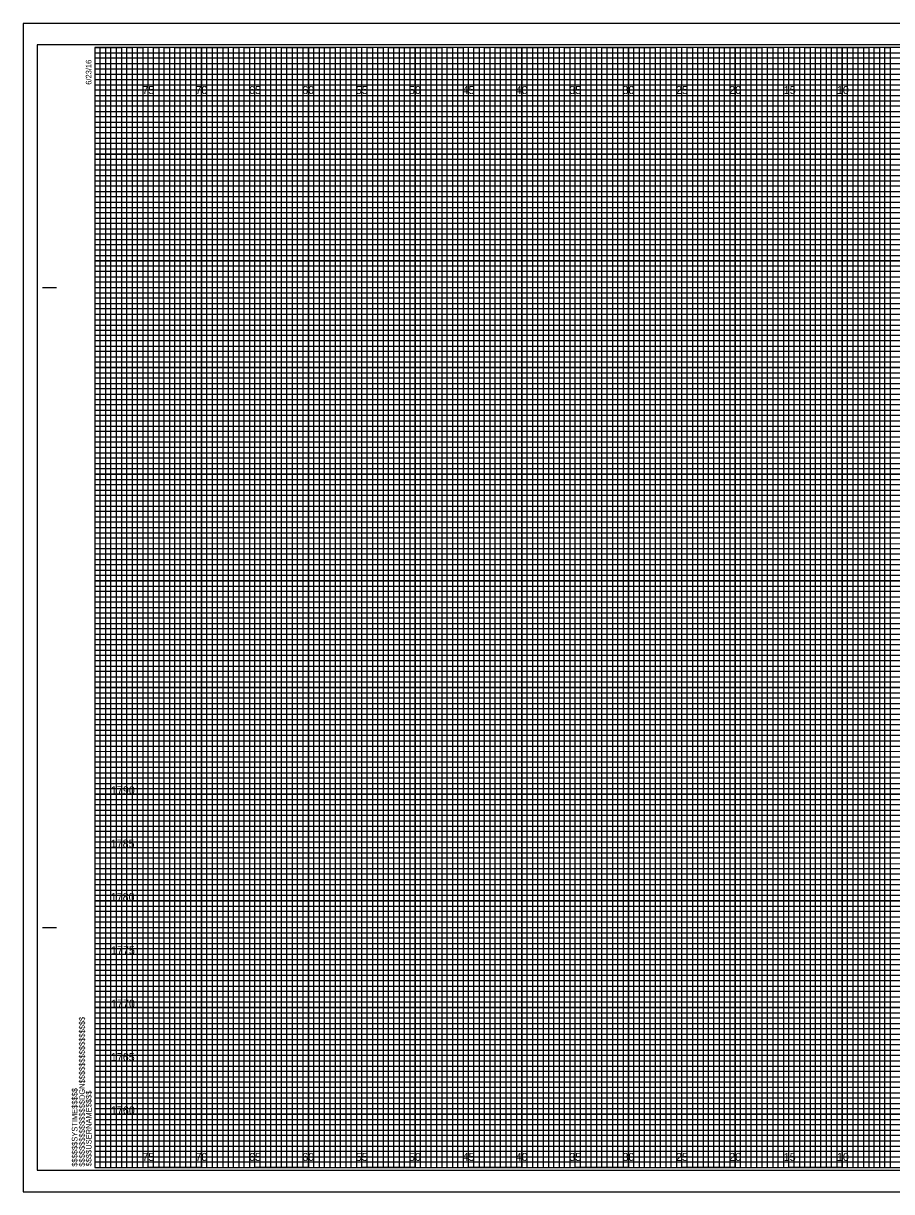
# Model space of a CAD drawing. Extents: x 224 to 392, y 1 to 440.
# Drawn here: x 223.6 to 304.9, y 331 to 440.5 of the extents above; entities that cross this region are included whole.
import ezdxf

# ---------------------------------------------------------------- set-up
doc = ezdxf.new("R2010")
doc.units = 0
for name, color, linetype in [('Prop Grid Mask', 7, 'Continuous'), ('Prop XS Elevation Labels', 7, 'Continuous'), ('Sheet Cross Section CELL', 7, 'Continuous'), ('Sheet Cross Section Grid Major CELL', 7, 'Continuous'), ('Sheet Cross Section Grid Middle CELL', 7, 'Continuous'), ('Sheet Cross Section Grid Minor 1 CELL', 7, 'Continuous'), ('Sheet Cross Section Grid Minor 2 CELL', 7, 'Continuous'), ('Sheet Cutting Line CELL', 7, 'Continuous'), ('Sheet DOT Grid CELL', 7, 'Continuous'), ('Sheet Plot Border Inside CELL', 7, 'Continuous'), ('Sheet Plot Border Outside CELL', 7, 'Continuous')]:
    doc.layers.add(name, color=color, linetype=linetype)

msp = doc.modelspace()

# ---------------------------------------------------------------- linework, layer by layer
at = {"layer": 'Sheet Cross Section CELL'}
for p, q in [((225.36, 415.71), (226.61, 415.71)), ((225.41, 415.71), (226.66, 415.71)), ((225.36, 355.71), (226.61, 355.71)), ((225.41, 355.71), (226.66, 355.71)), ((230.26, 333.21), (230.26, 333.21)), ((230.26, 333.21), (230.26, 333.21)), ((230.26, 333.21), (230.26, 333.21)), ((230.26, 333.21), (230.26, 333.21)), ((230.26, 333.21), (230.26, 333.21)), ((230.26, 333.21), (230.26, 333.21)), ((230.26, 333.21), (230.26, 333.21))]:
    msp.add_line(p, q, dxfattribs=at)
msp.add_lwpolyline([(390.26, 438.21), (230.26, 438.21), (230.26, 333.21), (390.26, 333.21)], close=True, dxfattribs=at)
at = {"layer": 'Sheet Cross Section Grid Major CELL'}
for p, q in [((235.26, 438.21), (230.26, 438.21)), ((235.26, 333.21), (235.26, 438.21)), ((245.26, 438.21), (240.26, 438.21)), ((240.26, 438.21), (240.26, 333.21)), ((245.26, 333.21), (245.26, 438.21)), ((255.26, 438.21), (250.26, 438.21)), ((250.26, 438.21), (250.26, 333.21)), ((255.26, 333.21), (255.26, 438.21)), ((265.26, 438.21), (260.26, 438.21)), ((260.26, 438.21), (260.26, 333.21)), ((265.26, 333.21), (265.26, 438.21)), ((275.26, 438.21), (270.26, 438.21)), ((270.26, 438.21), (270.26, 333.21)), ((275.26, 333.21), (275.26, 438.21)), ((285.26, 438.21), (280.26, 438.21)), ((280.26, 438.21), (280.26, 333.21)), ((285.26, 333.21), (285.26, 438.21)), ((295.26, 438.21), (290.26, 438.21)), ((290.26, 438.21), (290.26, 333.21)), ((295.26, 333.21), (295.26, 438.21)), ((305.26, 438.21), (300.26, 438.21)), ((300.26, 438.21), (300.26, 333.21)), ((240.26, 333.21), (235.26, 333.21)), ((250.26, 333.21), (245.26, 333.21)), ((260.26, 333.21), (255.26, 333.21)), ((270.26, 333.21), (265.26, 333.21)), ((280.26, 333.21), (275.26, 333.21)), ((290.26, 333.21), (285.26, 333.21)), ((300.26, 333.21), (295.26, 333.21))]:
    msp.add_line(p, q, dxfattribs=at)
for points in [[(230.26, 433.21), (390.26, 433.21), (390.26, 428.21), (230.26, 428.21)], [(230.26, 423.21), (390.26, 423.21), (390.26, 418.21), (230.26, 418.21)], [(230.26, 413.21), (390.26, 413.21), (390.26, 408.21), (230.26, 408.21)], [(230.26, 403.21), (390.26, 403.21), (390.26, 398.21), (230.26, 398.21)], [(230.26, 393.21), (390.26, 393.21), (390.26, 388.21), (230.26, 388.21)], [(230.26, 383.21), (390.26, 383.21), (390.26, 378.21), (230.26, 378.21)], [(230.26, 373.21), (390.26, 373.21), (390.26, 368.21), (230.26, 368.21)], [(230.26, 363.21), (390.26, 363.21), (390.26, 358.21), (230.26, 358.21)], [(230.26, 353.21), (390.26, 353.21), (390.26, 348.21), (230.26, 348.21)], [(230.26, 343.21), (390.26, 343.21), (390.26, 338.21), (230.26, 338.21)]]:
    msp.add_lwpolyline(points, dxfattribs=at)
at = {"layer": 'Sheet Cross Section Grid Middle CELL'}
for points in [[(230.26, 438.21), (232.76, 438.21), (232.76, 333.21), (237.76, 333.21), (237.76, 438.21), (242.76, 438.21), (242.76, 333.21), (247.76, 333.21), (247.76, 438.21), (252.76, 438.21), (252.76, 333.21), (257.76, 333.21), (257.76, 438.21), (262.76, 438.21), (262.76, 333.21), (267.76, 333.21), (267.76, 438.21), (272.76, 438.21), (272.76, 333.21), (277.76, 333.21), (277.76, 438.21), (282.76, 438.21), (282.76, 333.21), (287.76, 333.21), (287.76, 438.21), (292.76, 438.21), (292.76, 333.21), (297.76, 333.21), (297.76, 438.21), (302.76, 438.21), (302.76, 333.21), (307.76, 333.21)], [(230.26, 435.71), (367.76, 435.71)], [(230.26, 425.71), (390.26, 425.71), (390.26, 430.71), (230.26, 430.71)], [(230.26, 415.71), (390.26, 415.71), (390.26, 420.71), (230.26, 420.71)], [(230.26, 405.71), (390.26, 405.71), (390.26, 410.71), (230.26, 410.71)], [(230.26, 395.71), (390.26, 395.71), (390.26, 400.71), (230.26, 400.71)], [(230.26, 385.71), (390.26, 385.71), (390.26, 390.71), (230.26, 390.71)], [(230.26, 375.71), (390.26, 375.71), (390.26, 380.71), (230.26, 380.71)], [(230.26, 365.71), (390.26, 365.71), (390.26, 370.71), (230.26, 370.71)], [(230.26, 355.71), (390.26, 355.71), (390.26, 360.71), (230.26, 360.71)], [(230.26, 345.71), (390.26, 345.71), (390.26, 350.71), (230.26, 350.71)], [(230.26, 335.71), (390.26, 335.71), (390.26, 340.71), (230.26, 340.71)]]:
    msp.add_lwpolyline(points, dxfattribs=at)
at = {"layer": 'Sheet Cross Section Grid Minor 1 CELL'}
for p, q in [((230.26, 437.71), (360.26, 437.71)), ((360.26, 437.2), (230.26, 437.2)), ((230.26, 437.2), (230.26, 436.71)), ((230.26, 436.71), (360.26, 436.71)), ((360.26, 436.16), (230.26, 436.16)), ((230.26, 436.16), (230.26, 435.21)), ((230.26, 435.21), (390.26, 435.21))]:
    msp.add_line(p, q, dxfattribs=at)
for points in [[(230.26, 434.71), (365.26, 434.71), (390.26, 434.71), (390.26, 434.21), (230.26, 434.21)], [(230.26, 433.71), (390.26, 433.71), (390.26, 432.71), (230.26, 432.71)], [(230.26, 432.21), (390.26, 432.21), (390.26, 431.71), (230.26, 431.7)], [(230.26, 431.21), (390.26, 431.21), (390.26, 430.21), (230.26, 430.21)], [(230.26, 429.71), (390.26, 429.71), (390.26, 429.21), (230.26, 429.21)], [(230.26, 428.71), (390.26, 428.71), (390.26, 427.71), (230.26, 427.71)], [(230.26, 427.21), (390.26, 427.21), (390.26, 426.71), (230.26, 426.71)], [(230.26, 426.21), (390.26, 426.21), (390.26, 425.21), (230.26, 425.21)], [(230.26, 424.71), (390.26, 424.71), (390.26, 424.21), (230.26, 424.21)], [(230.26, 423.71), (390.26, 423.71), (390.26, 422.71), (230.26, 422.71)], [(230.26, 422.21), (390.26, 422.21), (390.26, 421.71), (230.26, 421.71)], [(230.26, 421.21), (390.26, 421.21), (390.26, 420.19), (390.26, 419.71), (390.26, 419.21), (230.26, 419.21)], [(230.26, 420.21), (390.26, 420.21), (390.26, 419.71), (230.26, 419.71)], [(230.26, 418.71), (390.26, 418.71), (390.26, 417.71), (230.26, 417.73)], [(230.26, 417.73), (390.26, 417.71), (390.26, 417.21), (230.26, 417.21)], [(230.26, 416.71), (390.26, 416.71), (390.26, 416.21), (230.26, 416.21)], [(230.26, 415.21), (390.26, 415.21), (390.26, 414.71), (230.26, 414.71)], [(230.26, 414.21), (390.26, 414.21), (390.26, 413.71), (230.26, 413.71)], [(230.23, 412.66), (390.26, 412.66), (390.26, 412.15), (230.23, 412.15)], [(230.26, 411.71), (390.26, 411.71), (390.26, 411.21), (230.26, 411.21)], [(230.26, 410.21), (390.26, 410.21), (390.26, 409.71), (230.26, 409.71)], [(230.26, 409.21), (390.26, 409.21), (390.26, 408.71), (230.26, 408.71)], [(230.26, 407.71), (390.26, 407.71), (390.26, 407.21), (230.26, 407.21)], [(230.26, 406.71), (390.26, 406.71), (390.26, 406.21), (230.26, 406.21)], [(230.26, 405.21), (390.26, 405.21), (390.26, 404.71), (230.26, 404.71)], [(230.26, 404.21), (390.26, 404.21), (390.26, 403.71), (230.26, 403.71)], [(230.26, 402.71), (390.26, 402.71), (390.26, 402.2), (230.26, 402.21)], [(230.26, 401.71), (390.26, 401.71), (390.26, 401.21), (230.26, 401.21)], [(230.26, 400.21), (390.26, 400.21), (390.26, 399.71), (230.26, 399.71)], [(230.26, 399.21), (390.26, 399.21), (390.26, 398.71), (230.26, 398.71)], [(230.26, 397.71), (390.26, 397.71), (390.26, 397.21), (230.26, 397.21)], [(230.26, 396.71), (390.26, 396.71), (390.26, 396.21), (230.26, 396.21)], [(230.26, 395.21), (390.26, 395.21), (390.26, 394.71), (230.26, 394.71)], [(230.26, 394.21), (390.26, 394.21), (390.26, 393.71), (230.26, 393.71)], [(230.26, 392.71), (390.26, 392.71), (390.26, 392.21), (230.26, 392.21)], [(230.26, 391.71), (390.3, 391.67), (390.26, 391.21), (230.26, 391.21)], [(230.26, 390.21), (390.26, 390.21), (390.26, 389.71), (230.26, 389.71)], [(230.26, 389.21), (390.26, 389.21), (390.26, 388.71), (230.26, 388.71)], [(230.26, 387.71), (390.26, 387.71), (390.26, 387.21), (230.26, 387.21)], [(230.26, 386.71), (390.26, 386.71), (390.26, 386.21), (230.26, 386.21)], [(230.26, 385.21), (390.26, 385.21), (390.26, 384.71), (230.26, 384.71)], [(230.26, 384.21), (390.26, 384.21), (390.26, 383.71), (230.26, 383.71)], [(230.26, 382.71), (390.26, 382.71), (390.26, 382.21), (230.26, 382.21)], [(230.26, 381.71), (390.26, 381.71), (390.26, 381.21), (230.26, 381.21)], [(230.26, 380.21), (390.26, 380.21), (390.26, 379.71), (230.26, 379.71)], [(230.26, 379.21), (390.26, 379.21), (390.26, 378.71), (230.26, 378.71)], [(230.26, 377.71), (390.26, 377.71), (390.26, 377.21), (230.26, 377.21)], [(230.26, 376.71), (390.26, 376.71), (390.26, 376.21), (230.26, 376.21)], [(230.26, 375.21), (390.26, 375.21), (390.26, 374.71), (230.26, 374.71)], [(230.26, 374.21), (390.26, 374.21), (390.26, 373.71), (230.26, 373.71)], [(230.26, 372.71), (390.26, 372.71), (390.26, 372.2), (230.26, 372.21)], [(230.26, 371.71), (390.26, 371.71), (390.26, 371.21), (230.26, 371.21)], [(230.26, 370.21), (390.26, 370.21), (390.26, 369.71), (230.26, 369.71)], [(230.26, 369.21), (390.26, 369.21), (390.26, 368.71), (230.26, 368.71)], [(230.26, 367.71), (390.26, 367.71), (390.26, 367.21), (230.26, 367.21)], [(230.26, 366.71), (390.26, 366.71), (390.26, 366.21), (230.26, 366.21)], [(230.26, 365.21), (390.26, 365.21), (390.26, 364.71), (230.26, 364.71)], [(230.26, 364.21), (390.26, 364.21), (390.26, 363.71), (230.26, 363.71)], [(230.26, 362.71), (390.26, 362.71), (390.26, 362.21), (230.26, 362.21)], [(230.26, 361.71), (390.3, 361.67), (390.26, 361.21), (230.26, 361.21)], [(230.26, 360.21), (390.26, 360.21), (390.26, 359.71), (230.26, 359.71)], [(230.26, 359.21), (390.26, 359.21), (390.26, 358.71), (230.26, 358.71)], [(230.26, 357.71), (390.26, 357.71), (390.26, 357.21), (230.26, 357.21)], [(230.26, 356.71), (390.26, 356.71), (390.26, 356.21), (230.26, 356.21)], [(230.26, 355.21), (390.26, 355.21), (390.26, 354.71), (230.26, 354.71)], [(230.26, 354.21), (390.26, 354.21), (390.26, 353.71), (230.26, 353.71)], [(230.26, 352.71), (390.26, 352.71), (390.26, 352.21), (230.26, 352.21)], [(230.26, 351.71), (390.26, 351.71), (390.26, 351.21), (230.26, 351.21)], [(230.26, 350.21), (390.26, 350.21), (390.26, 349.71), (230.26, 349.71)], [(230.26, 349.21), (390.26, 349.21), (390.26, 348.71), (230.26, 348.71)], [(230.26, 347.71), (390.26, 347.71), (390.26, 347.21), (230.26, 347.21)], [(230.26, 346.71), (390.26, 346.71), (390.26, 346.21), (230.26, 346.21)], [(230.26, 345.21), (390.26, 345.21), (390.26, 344.71), (230.26, 344.71)], [(230.26, 344.21), (390.26, 344.21), (390.26, 343.71), (230.26, 343.71)], [(230.26, 342.71), (390.26, 342.71), (390.26, 342.21), (230.26, 342.21)], [(230.26, 341.71), (390.26, 341.71), (390.26, 341.21), (230.26, 341.21)], [(230.26, 340.21), (390.26, 340.21), (390.26, 339.71), (230.26, 339.71)], [(230.26, 339.21), (390.26, 339.21), (390.26, 338.71), (230.26, 338.71)], [(230.26, 337.71), (390.26, 337.71), (390.26, 337.21), (230.26, 337.21)], [(230.26, 336.71), (390.26, 336.71), (390.26, 336.21), (230.26, 336.21)], [(230.26, 335.21), (390.26, 335.21), (390.26, 334.71), (230.26, 334.71)], [(230.26, 334.21), (390.26, 334.21), (390.26, 333.71), (230.26, 333.71)]]:
    msp.add_lwpolyline(points, dxfattribs=at)
at = {"layer": 'Sheet Cross Section Grid Minor 2 CELL'}
for points in [[(230.26, 333.21), (230.76, 333.21), (230.76, 438.21), (231.26, 438.21), (231.26, 333.21)], [(231.26, 333.21), (231.76, 333.21), (231.76, 438.21), (232.26, 438.21), (232.26, 333.21)], [(232.76, 333.21), (233.26, 333.21), (233.26, 438.21), (233.76, 438.21), (233.76, 333.21)], [(233.76, 333.21), (234.26, 333.21), (234.26, 438.21), (234.76, 438.21), (234.76, 333.21)], [(235.26, 333.21), (235.76, 333.21), (235.76, 438.21), (236.26, 438.21), (236.26, 333.21)], [(236.26, 333.21), (236.76, 333.21), (236.76, 438.21), (237.26, 438.21), (237.26, 333.21)], [(237.76, 333.21), (238.26, 333.21), (238.26, 438.21), (238.76, 438.21), (238.76, 333.21)], [(238.76, 333.21), (239.26, 333.21), (239.26, 438.21), (239.76, 438.21), (239.76, 333.21)], [(240.26, 333.21), (240.76, 333.21), (240.76, 438.21), (241.26, 438.21), (241.26, 333.21)], [(241.26, 333.21), (241.76, 333.21), (241.76, 438.21), (242.26, 438.21), (242.26, 333.21)], [(242.76, 333.21), (243.26, 333.21), (243.26, 438.21), (243.76, 438.21), (243.76, 333.21)], [(243.76, 333.21), (244.26, 333.21), (244.26, 438.21), (244.76, 438.21), (244.76, 333.21)], [(245.26, 333.21), (245.76, 333.21), (245.76, 438.21), (246.26, 438.21), (246.26, 333.21)], [(246.26, 333.21), (246.76, 333.21), (246.76, 438.21), (247.26, 438.21), (247.26, 333.21)], [(247.76, 333.21), (248.26, 333.21), (248.26, 438.21), (248.76, 438.21), (248.76, 333.21)], [(248.76, 333.21), (249.26, 333.21), (249.26, 438.21), (249.76, 438.21), (249.76, 333.21)], [(250.26, 333.21), (250.76, 333.21), (250.76, 438.21), (251.26, 438.21), (251.26, 333.21)], [(251.26, 333.21), (251.76, 333.21), (251.76, 438.21), (252.26, 438.21), (252.26, 333.21)], [(252.76, 333.21), (253.26, 333.21), (253.26, 438.21), (253.76, 438.21), (253.76, 333.21)], [(253.76, 333.21), (254.26, 333.21), (254.26, 438.21), (254.76, 438.21), (254.76, 333.21)], [(255.26, 333.21), (255.76, 333.21), (255.76, 438.21), (256.26, 438.21), (256.26, 333.21)], [(256.26, 333.21), (256.76, 333.21), (256.76, 438.21), (257.26, 438.21), (257.26, 333.21)], [(257.76, 333.21), (258.26, 333.21), (258.26, 438.21), (258.76, 438.21), (258.76, 333.21)], [(258.76, 333.21), (259.26, 333.21), (259.26, 438.21), (259.76, 438.21), (259.76, 333.21)], [(260.26, 333.21), (260.76, 333.21), (260.76, 438.21), (261.26, 438.21), (261.26, 333.21)], [(261.26, 333.21), (261.76, 333.21), (261.76, 438.21), (262.26, 438.21), (262.26, 333.21)], [(262.76, 333.21), (263.26, 333.21), (263.26, 438.21), (263.76, 438.21), (263.76, 333.21)], [(263.76, 333.21), (264.26, 333.21), (264.26, 438.21), (264.76, 438.21), (264.76, 333.21)], [(265.26, 333.21), (265.76, 333.21), (265.76, 438.21), (266.26, 438.21), (266.26, 333.21)], [(266.26, 333.21), (266.76, 333.21), (266.76, 438.21), (267.26, 438.21), (267.26, 333.21)], [(267.76, 333.21), (268.26, 333.21), (268.26, 438.21), (268.76, 438.21), (268.76, 333.21)], [(268.76, 333.21), (269.26, 333.21), (269.26, 438.21), (269.76, 438.21), (269.76, 333.21)], [(270.26, 333.21), (270.76, 333.21), (270.76, 438.21), (271.26, 438.21), (271.26, 333.21)], [(271.26, 333.21), (271.76, 333.21), (271.76, 438.21), (272.26, 438.21), (272.26, 333.21)], [(272.76, 333.21), (273.26, 333.21), (273.26, 438.21), (273.76, 438.21), (273.76, 333.21)], [(273.76, 333.21), (274.26, 333.21), (274.26, 438.21), (274.76, 438.21), (274.76, 333.21)], [(275.26, 333.21), (275.76, 333.21), (275.76, 438.21), (276.26, 438.21), (276.26, 333.21)], [(276.26, 333.21), (276.76, 333.21), (276.76, 438.21), (277.26, 438.21), (277.26, 333.21)], [(277.76, 333.21), (278.26, 333.21), (278.26, 438.21), (278.76, 438.21), (278.76, 333.21)], [(278.76, 333.21), (279.26, 333.21), (279.26, 438.21), (279.76, 438.21), (279.76, 333.21)], [(280.26, 333.21), (280.76, 333.21), (280.76, 438.21), (281.26, 438.21), (281.26, 333.21)], [(281.26, 333.21), (281.76, 333.21), (281.76, 438.21), (282.26, 438.21), (282.26, 333.21)], [(282.76, 333.21), (283.26, 333.21), (283.26, 438.21), (283.76, 438.21), (283.76, 333.21)], [(283.76, 333.21), (284.26, 333.21), (284.26, 438.21), (284.76, 438.21), (284.76, 333.21)], [(285.26, 333.21), (285.76, 333.21), (285.76, 438.21), (286.26, 438.21), (286.26, 333.21)], [(286.26, 333.21), (286.76, 333.21), (286.76, 438.21), (287.26, 438.21), (287.26, 333.21)], [(287.76, 333.21), (288.26, 333.21), (288.26, 438.21), (288.76, 438.21), (288.76, 333.21)], [(288.76, 333.21), (289.26, 333.21), (289.26, 438.21), (289.76, 438.21), (289.76, 333.21)], [(290.26, 333.21), (290.76, 333.21), (290.76, 438.21), (291.26, 438.21), (291.26, 333.21)], [(291.26, 333.21), (291.76, 333.21), (291.76, 438.21), (292.26, 438.21), (292.26, 333.21)], [(292.76, 333.21), (293.26, 333.21), (293.26, 438.21), (293.76, 438.21), (293.76, 333.21)], [(293.76, 333.21), (294.26, 333.21), (294.26, 438.21), (294.76, 438.21), (294.76, 333.21)], [(295.26, 333.21), (295.76, 333.21), (295.76, 438.21), (296.26, 438.21), (296.26, 333.21)], [(296.26, 333.21), (296.76, 333.21), (296.76, 438.21), (297.26, 438.21), (297.26, 333.21)], [(297.76, 333.21), (298.26, 333.21), (298.26, 438.21), (298.76, 438.21), (298.76, 333.21)], [(298.76, 333.21), (299.26, 333.21), (299.26, 438.21), (299.76, 438.21), (299.76, 333.21)], [(300.26, 333.21), (300.76, 333.21), (300.76, 438.21), (301.26, 438.21), (301.26, 333.21)], [(301.26, 333.21), (301.76, 333.21), (301.76, 438.21), (302.26, 438.21), (302.26, 333.21)], [(302.76, 333.21), (303.26, 333.21), (303.26, 438.21), (303.76, 438.21), (303.76, 333.21)], [(303.76, 333.21), (304.26, 333.21), (304.26, 438.21), (304.76, 438.21), (304.76, 333.21)]]:
    msp.add_lwpolyline(points, dxfattribs=at)
at = {"layer": 'Sheet Cutting Line CELL'}
for p, q in [((391.91, 440.46), (223.56, 440.46)), ((223.56, 440.46), (223.56, 330.96)), ((223.56, 330.96), (391.91, 330.96))]:
    msp.add_line(p, q, dxfattribs=at)
at = {"layer": 'Sheet DOT Grid CELL'}
for p, q in [((235.26, 333.21), (235.26, 438.21)), ((240.26, 333.21), (240.26, 438.21)), ((245.26, 333.21), (245.26, 438.21)), ((250.26, 333.21), (250.26, 438.21)), ((255.26, 333.21), (255.26, 438.21)), ((260.26, 333.21), (260.26, 438.21)), ((265.26, 333.21), (265.26, 438.21)), ((270.26, 333.21), (270.26, 438.21)), ((275.26, 333.21), (275.26, 438.21)), ((280.26, 333.21), (280.26, 438.21)), ((285.26, 333.21), (285.26, 438.21)), ((290.26, 333.21), (290.26, 438.21)), ((295.26, 333.21), (295.26, 438.21)), ((300.26, 333.21), (300.26, 438.21)), ((230.26, 433.21), (390.26, 433.21)), ((230.26, 428.21), (390.26, 428.21)), ((230.26, 423.21), (390.26, 423.21)), ((230.26, 418.21), (390.26, 418.21)), ((230.26, 413.21), (390.26, 413.21)), ((230.26, 408.21), (390.26, 408.21)), ((230.26, 403.21), (390.26, 403.21)), ((230.26, 398.21), (390.26, 398.21)), ((230.26, 393.21), (390.26, 393.21)), ((230.26, 388.21), (390.26, 388.21)), ((230.26, 383.21), (390.26, 383.21)), ((230.26, 378.21), (390.26, 378.21)), ((230.26, 373.21), (390.26, 373.21)), ((230.26, 368.21), (390.26, 368.21)), ((230.26, 363.21), (390.26, 363.21)), ((230.26, 358.21), (390.26, 358.21)), ((230.26, 353.21), (390.26, 353.21)), ((230.26, 348.21), (390.26, 348.21)), ((230.26, 343.21), (390.26, 343.21)), ((230.26, 338.21), (390.26, 338.21))]:
    msp.add_line(p, q, dxfattribs=at)
at = {"layer": 'Sheet Plot Border Inside CELL'}
msp.add_lwpolyline([(224.86, 332.96), (391.46, 332.96), (391.46, 438.46), (224.86, 438.46)], close=True, dxfattribs=at)
at = {"layer": 'Sheet Plot Border Outside CELL'}
msp.add_lwpolyline([(223.56, 330.96), (391.91, 330.96), (391.91, 440.46), (223.56, 440.46)], close=True, dxfattribs=at)

# ---------------------------------------------------------------- texts
at = {"layer": 'Prop Grid Mask'}
for s, p in [('75', (234.71, 433.84)), ('70', (239.69, 433.84)), ('65', (244.71, 433.84)), ('60', (249.69, 433.84)), ('55', (254.71, 433.84)), ('50', (259.69, 433.84)), ('45', (264.71, 433.84)), ('40', (269.69, 433.84)), ('35', (274.71, 433.84)), ('30', (279.69, 433.84)), ('25', (284.71, 433.84)), ('20', (289.69, 433.84)), ('15', (294.8, 433.84)), ('10', (299.78, 433.84)), ('75', (234.71, 333.84)), ('70', (239.69, 333.84)), ('65', (244.71, 333.84)), ('60', (249.69, 333.84)), ('55', (254.71, 333.84)), ('50', (259.69, 333.84)), ('45', (264.71, 333.84)), ('40', (269.69, 333.84)), ('35', (274.71, 333.84)), ('30', (279.69, 333.84)), ('25', (284.71, 333.84)), ('20', (289.69, 333.84)), ('15', (294.8, 333.84)), ('10', (299.78, 333.84))]:
    msp.add_text(s, height=0.75, dxfattribs=at).set_placement(p)
at = {"layer": 'Prop XS Elevation Labels'}
for s, p in [('1790', (231.77, 368.21)), ('1785', (231.75, 363.21)), ('1780', (231.75, 358.21)), ('1775', (231.78, 353.21)), ('1770', (231.78, 348.21)), ('1765', (231.76, 343.21)), ('1760', (231.77, 338.21))]:
    msp.add_text(s, height=0.75, dxfattribs=at).set_placement(p)
at = {"layer": 'Sheet Cross Section CELL'}
for s, p in [('6/23/16', (229.94, 434.71)), ('$$$$$$$$$$$$$$$$DGN$$$$$$$$$$$$$$$$', (229.32, 333.3)), ('$$$$$$SYSTIME$$$$$', (228.63, 333.3)), ('$$$$USERNAME$$$$', (229.95, 333.33))]:
    msp.add_text(s, height=0.525, rotation=90, dxfattribs=at).set_placement(p)

doc.saveas('drawing.dxf')
